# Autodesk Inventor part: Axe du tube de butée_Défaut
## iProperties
Shininess: 64.0
Length Units: 11269
Angle Units: 11279
Time Units: 11290
Mass Units: 11283
Length Display Precision: 3
Angle Display Precision: 2
Compacted: True
Part Number: Axe du tube de butée_Défaut
Document SubType Name: Modeling
Created: 2006-11
Material: Par défaut
Designer: profs_sti
Density: 0.0
Volumn: 0.0
Area: 0.0
PropertySet Name: Model Information
Control State: 0
Master: False
Checked Out: False
Author: profs_sti
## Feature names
1. Base1
